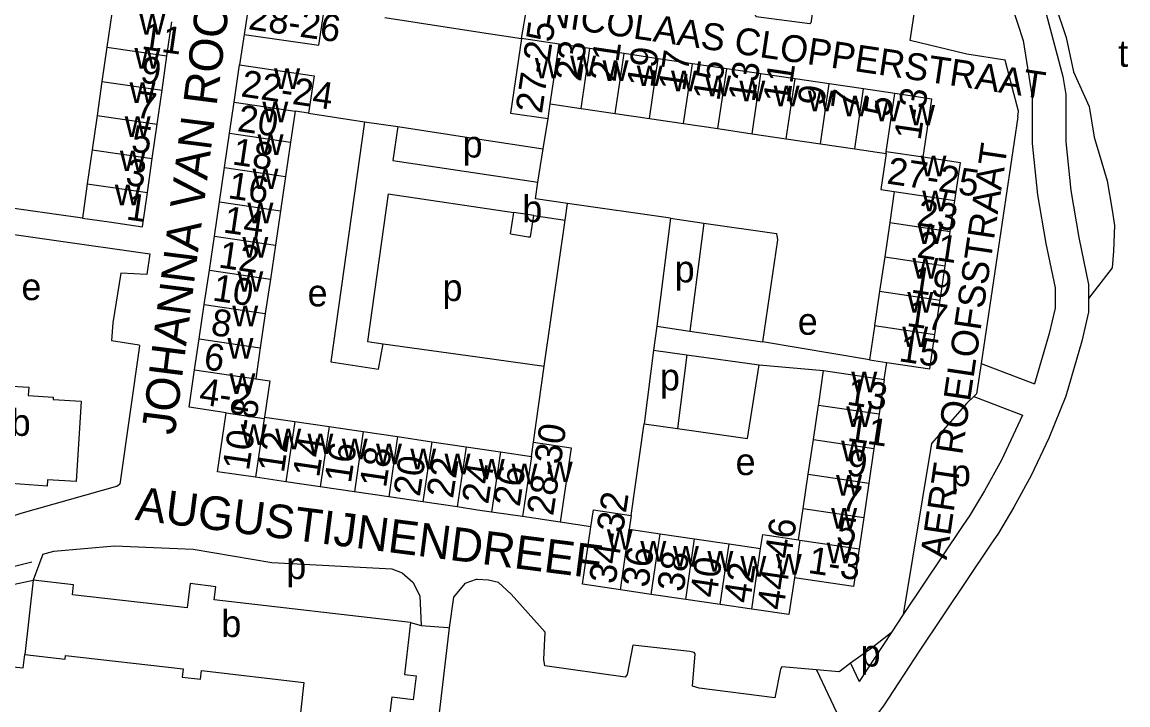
# Model space of a CAD drawing. Extents: x 160673 to 161924, y 382258 to 384145.
# Drawn here: x 161759.3 to 161924, y 383291.6 to 383393.3 of the extents above; entities that cross this region are included whole.
import ezdxf

# ---------------------------------------------------------------- set-up
doc = ezdxf.new("R2010")
doc.units = 0
for name, color, linetype in [('BLT_Basislijn', 7, 'Continuous'), ('BLT_Bebouwing', 7, 'Continuous'), ('BLT_Centroide', 7, 'Continuous'), ('BLT_Huisnummer', 7, 'Continuous'), ('BLT_Huisnummer_ tussenligend', 7, 'Continuous'), ('BLT_Huisnummer_reeks', 7, 'Continuous'), ('BLT_Onderverdeling_panden', 7, 'Continuous'), ('BLT_Straatnaam', 7, 'Continuous')]:
    doc.layers.add(name, color=color, linetype=linetype)

msp = doc.modelspace()

# ---------------------------------------------------------------- linework, layer by layer
at = {"layer": 'BLT_Basislijn'}
for p, q in [((161910.64, 383398.88), (161914.28, 383385.18)), ((161833.69, 383390.85), (161834.53, 383395.69)), ((161813.36, 383393.96), (161827.12, 383391.85)), ((161792.41, 383391.46), (161791.72, 383386.93)), ((161827.12, 383391.85), (161833.69, 383390.85)), ((161801.98, 383379.72), (161810.29, 383378.43)), ((161810.29, 383378.43), (161815.25, 383377.73)), ((161815.25, 383377.73), (161827.12, 383375.9)), ((161836.93, 383374.42), (161837.64, 383378.92)), ((161907.59, 383379.17), (161902.11, 383342.46)), ((161827.12, 383375.9), (161836.93, 383374.42)), ((161814.54, 383372.69), (161836.12, 383369.44)), ((161768.3, 383364.09), (161751.58, 383366.42)), ((161813.85, 383367.73), (161832.55, 383364.92)), ((161840.19, 383363.78), (161840.55, 383366.25)), ((161855.89, 383364.07), (161840.55, 383366.25)), ((161835.51, 383364.48), (161840.19, 383363.78)), ((161837.07, 383342.05), (161840.19, 383363.78)), ((161855.89, 383364.07), (161853.82, 383348)), ((161860.84, 383363.35), (161858.77, 383347.26)), ((161853.82, 383348), (161853.36, 383344.42)), ((161853.82, 383348), (161858.77, 383347.26)), ((161858.77, 383347.26), (161869.55, 383345.67)), ((161912.25, 383346.91), (161910.08, 383339.43)), ((161810.77, 383345.72), (161813.07, 383345.38)), ((161885.49, 383342.99), (161869.55, 383345.67)), ((161853.36, 383344.42), (161851.94, 383333.46)), ((161853.36, 383344.42), (161858.31, 383343.74)), ((161858.31, 383343.74), (161856.89, 383332.76)), ((161858.31, 383343.74), (161869.07, 383342.25)), ((161835.49, 383330.72), (161837.07, 383342.05)), ((161869.07, 383342.25), (161878.66, 383341.39)), ((161887.67, 383340.06), (161888.08, 383342.6)), ((161902.11, 383342.46), (161910.08, 383339.43)), ((161901.02, 383337.52), (161908.29, 383334.76)), ((161844.02, 383318.12), (161839.43, 383318.81)), ((161900.41, 383319.74), (161899.4, 383318.32)), ((161899.4, 383318.32), (161890.52, 383305.06)), ((161904.71, 383317.19), (161903.55, 383315.54)), ((161762.43, 383314.06), (161760.99, 383310.16)), ((161735.45, 383304.68), (161760.99, 383310.16)), ((161817.16, 383303.88), (161818.73, 383303.41)), ((161890.52, 383305.06), (161888.7, 383302.33)), ((161822.9, 383303.08), (161820.7, 383284.23)), ((161888.7, 383302.33), (161883.96, 383295.09)), ((161888.7, 383302.33), (161885.74, 383300.01)), ((161885.74, 383300.01), (161882.69, 383297.79)), ((161882.69, 383297.79), (161881.11, 383296.63)), ((161882.69, 383297.79), (161883.96, 383295.09)), ((161877.63, 383296.8), (161880.58, 383290.53))]:
    msp.add_line(p, q, dxfattribs=at)
for points in [[(161906.73, 383383.61), (161905.69, 383387.62), (161900, 383388.49), (161891.56, 383390.53), (161892.17, 383394.49), (161892.14, 383395.41), (161877.7, 383397.48), (161877.33, 383396.85), (161876.77, 383393.18), (161876.62, 383393.02), (161868.62, 383394.06), (161868.41, 383394.58), (161868.79, 383398.92), (161858.84, 383400.41)], [(161913.04, 383396.17), (161914.76, 383391.02), (161915.88, 383385.88)], [(161906.69, 383395.71), (161908.37, 383390.55), (161909.71, 383382.11), (161909.71, 383375.2), (161910.5, 383367.55), (161911.76, 383360.3), (161913.12, 383353.69), (161913.12, 383350.66), (161912.25, 383346.91)], [(161914.28, 383385.18), (161914.71, 383382.5), (161914.71, 383375.46), (161915.46, 383368.23), (161916.68, 383361.23), (161918.12, 383354.2), (161918.12, 383352.14)], [(161915.88, 383385.88), (161918.19, 383380.72), (161918.95, 383376.14), (161920.1, 383372.33), (161920.86, 383369.66), (161921.62, 383365.27), (161922, 383362.98), (161921.81, 383359.17), (161921.62, 383356.69), (161918.12, 383352.14)], [(161907.59, 383379.17), (161907.66, 383380.01), (161906.73, 383383.61)], [(161810.29, 383378.43), (161805.29, 383342.67), (161812.41, 383341.6), (161813.07, 383345.38)], [(161815.25, 383377.73), (161814.54, 383372.69)], [(161836.12, 383369.44), (161836.93, 383374.42)], [(161840.55, 383366.25), (161835.75, 383366.97), (161836.12, 383369.44)], [(161813.85, 383367.73), (161810.77, 383345.72)], [(161749.04, 383362.95), (161778.36, 383358.76), (161777.91, 383355.7), (161774.02, 383355.88), (161772.83, 383348.49), (161772.64, 383345.85), (161776.77, 383345.22), (161776.81, 383345.06), (161773.87, 383324.47), (161773.55, 383324.15), (161759.14, 383320.1), (161749.36, 383316.93), (161746.78, 383315.85), (161746.52, 383315.82)], [(161855.89, 383364.07), (161860.84, 383363.35)], [(161860.84, 383363.35), (161871.66, 383361.79), (161871.78, 383360.86), (161869.55, 383345.67)], [(161918.12, 383352.14), (161918.12, 383350.09), (161917.12, 383345.79)], [(161813.07, 383345.38), (161827.12, 383343.43)], [(161917.12, 383345.79), (161914.74, 383337.59), (161912.21, 383331.34), (161909.59, 383325.78), (161906.98, 383321.02), (161904.71, 383317.19)], [(161827.12, 383343.43), (161837.07, 383342.05)], [(161856.89, 383332.76), (161867.34, 383331.29), (161869.07, 383342.25)], [(161902.11, 383342.46), (161901.43, 383337.91), (161901.02, 383337.52)], [(161901.02, 383337.52), (161900, 383336.53), (161894.72, 383330.52), (161890.52, 383305.06)], [(161850.03, 383319.82), (161851.9, 383333.14), (161851.94, 383333.46)], [(161851.94, 383333.46), (161856.89, 383332.76)], [(161908.29, 383334.76), (161905.14, 383328.05), (161902.64, 383323.5), (161900.41, 383319.74)], [(161762.43, 383314.06), (161764.05, 383314.47), (161773.07, 383315.29), (161784.8, 383314.81), (161796.49, 383312.82), (161814.4, 383311.87), (161815.93, 383311.26), (161817.53, 383309.87), (161818.55, 383307.86), (161818.73, 383303.41)], [(161903.55, 383315.54), (161892.87, 383299.58), (161887.56, 383291.45), (161871.44, 383270.22)], [(161724.18, 383306.34), (161743.3, 383308.59), (161760.8, 383312.91)], [(161827.12, 383310.26), (161826.93, 383310.27), (161825.24, 383309.65), (161823.58, 383307.64), (161822.9, 383303.08)], [(161877.63, 383296.8), (161872.45, 383297.25), (161872.23, 383296.93), (161871.39, 383292.66), (161860.14, 383294.06), (161859.15, 383294.38), (161859.53, 383299.2), (161859.37, 383299.42), (161858.74, 383299.55), (161850.24, 383300.5), (161849.43, 383296.14), (161849.14, 383295.74), (161837.17, 383297.41), (161837.01, 383298.34), (161837.19, 383302.45), (161832.13, 383308.11), (161830.28, 383309.8), (161828.77, 383310.18), (161827.12, 383310.26)], [(161818.73, 383303.41), (161822.71, 383303.1), (161822.9, 383303.08)], [(161755, 383255.26), (161713.93, 383272.22), (161717.48, 383287.8), (161719.8, 383288.64), (161720.55, 383285.11), (161755.9, 383292.8), (161754.93, 383297.3), (161756.03, 383297.45), (161759.51, 383297.13), (161759.73, 383299.08)], [(161881.11, 383296.63), (161880.95, 383296.52), (161877.63, 383296.8)]]:
    msp.add_lwpolyline(points, dxfattribs=at)
at = {"layer": 'BLT_Bebouwing'}
for p, q in [((161793.23, 383397.06), (161792.41, 383391.46)), ((161772.68, 383394.62), (161771.95, 383389.54)), ((161780.9, 383388.26), (161781.63, 383393.34)), ((161839.28, 383390.02), (161833.69, 383390.85)), ((161771.95, 383389.54), (161771.22, 383384.45)), ((161843.87, 383389.35), (161839.28, 383390.02)), ((161848.96, 383388.59), (161843.87, 383389.35)), ((161780.17, 383383.17), (161780.9, 383388.26)), ((161854.05, 383387.84), (161848.96, 383388.59)), ((161859.15, 383387.09), (161854.05, 383387.84)), ((161790.9, 383381.36), (161791.72, 383386.93)), ((161864.24, 383386.34), (161859.15, 383387.09)), ((161869.33, 383385.58), (161864.24, 383386.34)), ((161771.22, 383384.45), (161770.49, 383379.36)), ((161874.42, 383384.83), (161869.33, 383385.58)), ((161879.51, 383384.08), (161874.42, 383384.83)), ((161779.44, 383378.08), (161780.17, 383383.17)), ((161884.61, 383383.33), (161879.51, 383384.08)), ((161889.28, 383382.64), (161884.61, 383383.33)), ((161790.22, 383376.73), (161790.9, 383381.36)), ((161837.64, 383378.92), (161837.97, 383381.11)), ((161837.97, 383381.11), (161842.55, 383380.43)), ((161770.49, 383379.36), (161769.76, 383374.27)), ((161799.99, 383380.02), (161799.3, 383375.39)), ((161801.98, 383379.72), (161799.99, 383380.02)), ((161847.64, 383379.68), (161852.74, 383378.92)), ((161778.71, 383372.99), (161779.44, 383378.08)), ((161852.74, 383378.92), (161857.83, 383378.17)), ((161857.83, 383378.17), (161862.92, 383377.42)), ((161789.46, 383371.63), (161790.22, 383376.73)), ((161862.92, 383377.42), (161868.01, 383376.67)), ((161868.01, 383376.67), (161873.1, 383375.91)), ((161873.1, 383375.91), (161878.2, 383375.16)), ((161878.2, 383375.16), (161883.29, 383374.41)), ((161883.29, 383374.41), (161887.96, 383373.72)), ((161769.76, 383374.27), (161769.03, 383369.18)), ((161777.98, 383367.9), (161778.71, 383372.99)), ((161788.71, 383366.53), (161789.46, 383371.63)), ((161798.55, 383370.29), (161797.8, 383365.19)), ((161769.03, 383369.18), (161768.3, 383364.09)), ((161889.19, 383368.06), (161888.51, 383363.44)), ((161787.96, 383361.43), (161788.71, 383366.53)), ((161897.52, 383362.11), (161898.2, 383366.73)), ((161797.8, 383365.19), (161797.05, 383360.09)), ((161832.07, 383361.73), (161832.55, 383364.92)), ((161835.51, 383364.48), (161832.55, 383364.92)), ((161888.51, 383363.44), (161887.76, 383358.33)), ((161787.21, 383356.33), (161787.96, 383361.43)), ((161896.77, 383357), (161897.52, 383362.11)), ((161797.05, 383360.09), (161796.3, 383354.99)), ((161887.76, 383358.33), (161887, 383353.22)), ((161786.46, 383351.23), (161787.21, 383356.33)), ((161896.01, 383351.89), (161896.77, 383357)), ((161796.3, 383354.99), (161795.54, 383349.89)), ((161887, 383353.22), (161886.24, 383348.1)), ((161895.25, 383346.77), (161896.01, 383351.89)), ((161785.7, 383346.13), (161786.46, 383351.23)), ((161795.54, 383349.89), (161794.79, 383344.79)), ((161785.02, 383341.51), (161785.7, 383346.13)), ((161794.79, 383344.79), (161794.11, 383340.17)), ((161885.49, 383342.99), (161888.08, 383342.6)), ((161878.66, 383341.39), (161887.67, 383340.06)), ((161887.67, 383340.06), (161886.92, 383334.92)), ((161877.15, 383331.11), (161877.9, 383336.25)), ((161886.92, 383334.92), (161886.16, 383329.78)), ((161795.41, 383334.47), (161799.93, 383333.8)), ((161799.93, 383333.8), (161805.03, 383333.05)), ((161805.03, 383333.05), (161810.13, 383332.3)), ((161810.13, 383332.3), (161815.24, 383331.55)), ((161815.24, 383331.55), (161820.34, 383330.79)), ((161820.34, 383330.79), (161825.44, 383330.04)), ((161835.17, 383328.61), (161835.49, 383330.72)), ((161876.39, 383325.97), (161877.15, 383331.11)), ((161830.55, 383329.29), (161835.17, 383328.61)), ((161886.16, 383329.78), (161885.4, 383324.64)), ((161798.6, 383324.83), (161794.09, 383325.49)), ((161875.63, 383320.84), (161876.39, 383325.97)), ((161803.71, 383324.08), (161798.6, 383324.83)), ((161808.81, 383323.32), (161803.71, 383324.08)), ((161813.91, 383322.57), (161808.81, 383323.32)), ((161885.4, 383324.64), (161884.64, 383319.51)), ((161819.02, 383321.82), (161813.91, 383322.57)), ((161824.12, 383321.07), (161819.02, 383321.82)), ((161827.12, 383320.62), (161824.12, 383321.07)), ((161829.22, 383320.31), (161827.12, 383320.62)), ((161833.85, 383319.63), (161829.22, 383320.31)), ((161874.94, 383316.17), (161875.63, 383320.84)), ((161839.43, 383318.81), (161833.85, 383319.63)), ((161850.03, 383319.82), (161849.74, 383317.76)), ((161884.64, 383319.51), (161883.95, 383314.84)), ((161849.74, 383317.76), (161854.34, 383317.08)), ((161859.46, 383316.33), (161864.59, 383315.57)), ((161864.59, 383315.57), (161869.29, 383314.88)), ((161883.95, 383314.84), (161883.13, 383309.23)), ((161760.99, 383310.16), (161759.73, 383299.08)), ((161883.13, 383309.23), (161874.31, 383310.53)), ((161853.01, 383308.06), (161848.41, 383308.74)), ((161858.13, 383307.31), (161853.01, 383308.06)), ((161863.26, 383306.55), (161858.13, 383307.31)), ((161867.96, 383305.86), (161863.26, 383306.55))]:
    msp.add_line(p, q, dxfattribs=at)
for points in [[(161792.41, 383391.46), (161803.51, 383389.84), (161804.33, 383395.43)], [(161833.69, 383390.85), (161832.05, 383379.74), (161837.64, 383378.92)], [(161791.72, 383386.93), (161802.8, 383385.3), (161801.98, 383379.72)], [(161893.51, 383373.15), (161894.79, 383381.82), (161889.28, 383382.64)], [(161842.55, 383380.43), (161842.91, 383380.37), (161847.64, 383379.68)], [(161799.3, 383375.39), (161799.26, 383375.07), (161798.55, 383370.29)], [(161887.96, 383373.72), (161887.17, 383368.36), (161889.19, 383368.06)], [(161898.2, 383366.73), (161899.03, 383372.34), (161893.51, 383373.15)], [(161768.3, 383364.09), (161772.3, 383363.52), (161777.25, 383362.81), (161777.98, 383367.9)], [(161832.07, 383361.73), (161834.71, 383361.33), (161835.02, 383361.29), (161835.51, 383364.48)], [(161886.24, 383348.1), (161886.22, 383347.93), (161885.49, 383342.99)], [(161888.08, 383342.6), (161894.5, 383341.65), (161895.25, 383346.77)], [(161789.69, 383335.11), (161784.2, 383335.92), (161785.02, 383341.51)], [(161794.11, 383340.17), (161796.21, 383339.86), (161795.41, 383334.47)], [(161877.9, 383336.25), (161877.93, 383336.44), (161878.66, 383341.39)], [(161747.91, 383338.11), (161751.9, 383337.85), (161751.92, 383338.2), (161756.91, 383337.88), (161756.99, 383339.13), (161760.32, 383338.92), (161760.24, 383337.67), (161763.97, 383337.43), (161763.94, 383337.08), (161768.15, 383336.81), (161767.38, 383324.85), (161763.13, 383325.12), (161763.07, 383324.19), (161750.97, 383325.05), (161751.04, 383325.99), (161747.07, 383326.28)], [(161794.09, 383325.49), (161788.4, 383326.33), (161789.69, 383335.11)], [(161825.44, 383330.04), (161827.12, 383329.79)], [(161835.49, 383330.72), (161841.06, 383329.9), (161839.43, 383318.81)], [(161827.12, 383329.79), (161830.23, 383329.33), (161830.55, 383329.29)], [(161844.02, 383318.12), (161844.39, 383320.65), (161850.03, 383319.82)], [(161848.41, 383308.74), (161842.76, 383309.58), (161844.02, 383318.12)], [(161854.34, 383317.08), (161854.68, 383317.03), (161859.46, 383316.33)], [(161869.29, 383314.88), (161869.6, 383316.96), (161874.94, 383316.17)], [(161817.16, 383303.88), (161787.92, 383307.23), (161788.17, 383309.2), (161784.35, 383309.68), (161783.89, 383306.04), (161766.83, 383307.98), (161766.99, 383309.47), (161760.99, 383310.16)], [(161874.31, 383310.53), (161873.51, 383305.04), (161867.96, 383305.86)], [(161817.16, 383303.88), (161816.27, 383296.13), (161817.99, 383295.94), (161817.58, 383292.35), (161814.38, 383292.72), (161808.98, 383249.99), (161808.89, 383249.27)], [(161759.73, 383299.08), (161765.73, 383298.39), (161765.8, 383298.97), (161783.31, 383296.96), (161783.16, 383295.74), (161785.9, 383295.41), (161786.05, 383296.7), (161801.29, 383294.95), (161799.69, 383280.5)]]:
    msp.add_lwpolyline(points, dxfattribs=at)
at = {"layer": 'BLT_Onderverdeling_panden'}
for p, q in [((161771.95, 383389.54), (161780.9, 383388.26)), ((161837.97, 383381.11), (161839.28, 383390.02)), ((161842.55, 383380.43), (161843.87, 383389.35)), ((161847.64, 383379.68), (161848.96, 383388.59)), ((161852.74, 383378.92), (161854.05, 383387.84)), ((161857.83, 383378.17), (161859.15, 383387.09)), ((161862.92, 383377.42), (161864.24, 383386.34)), ((161771.22, 383384.45), (161780.17, 383383.17)), ((161868.01, 383376.67), (161869.33, 383385.58)), ((161873.1, 383375.91), (161874.42, 383384.83)), ((161878.2, 383375.16), (161879.51, 383384.08)), ((161883.29, 383374.41), (161884.61, 383383.33)), ((161888, 383373.97), (161889.28, 383382.64)), ((161790.9, 383381.36), (161799.99, 383380.02)), ((161770.49, 383379.36), (161779.44, 383378.08)), ((161790.22, 383376.73), (161799.3, 383375.39)), ((161769.76, 383374.27), (161778.71, 383372.99)), ((161887.96, 383373.72), (161888, 383373.97)), ((161893.51, 383373.15), (161888, 383373.97)), ((161789.46, 383371.63), (161798.55, 383370.29)), ((161769.03, 383369.18), (161777.98, 383367.9)), ((161889.19, 383368.06), (161898.2, 383366.73)), ((161788.71, 383366.53), (161797.8, 383365.19)), ((161888.51, 383363.44), (161897.52, 383362.11)), ((161787.96, 383361.43), (161797.05, 383360.09)), ((161887.76, 383358.33), (161896.77, 383357)), ((161787.21, 383356.33), (161796.3, 383354.99)), ((161887, 383353.22), (161896.01, 383351.89)), ((161786.46, 383351.23), (161795.54, 383349.89)), ((161886.24, 383348.1), (161895.25, 383346.77)), ((161785.7, 383346.13), (161794.79, 383344.79)), ((161785.02, 383341.51), (161794.11, 383340.17)), ((161789.69, 383335.11), (161795.39, 383334.27)), ((161877.9, 383336.25), (161886.92, 383334.92)), ((161795.39, 383334.27), (161794.09, 383325.49)), ((161795.41, 383334.47), (161795.39, 383334.27)), ((161799.93, 383333.8), (161798.6, 383324.83)), ((161805.03, 383333.05), (161803.71, 383324.08)), ((161810.13, 383332.3), (161808.81, 383323.32)), ((161815.24, 383331.55), (161813.91, 383322.57)), ((161820.34, 383330.79), (161819.02, 383321.82)), ((161825.44, 383330.04), (161824.12, 383321.07)), ((161877.15, 383331.11), (161886.16, 383329.78)), ((161830.55, 383329.29), (161829.22, 383320.31)), ((161835.17, 383328.61), (161833.85, 383319.63)), ((161876.39, 383325.97), (161885.4, 383324.64)), ((161875.63, 383320.84), (161884.64, 383319.51)), ((161848.41, 383308.74), (161849.74, 383317.76)), ((161853.01, 383308.06), (161854.34, 383317.08)), ((161858.13, 383307.31), (161859.46, 383316.33)), ((161863.26, 383306.55), (161864.59, 383315.57)), ((161875.14, 383316.14), (161874.31, 383310.53)), ((161874.94, 383316.17), (161875.14, 383316.14)), ((161875.14, 383316.14), (161883.95, 383314.84)), ((161867.96, 383305.86), (161869.29, 383314.88))]:
    msp.add_line(p, q, dxfattribs=at)

# ---------------------------------------------------------------- texts
at = {"layer": 'BLT_Centroide'}
for s, p in [('w', (161776.79, 383391.44)), ('w', (161776.06, 383386.34)), ('t', (161922.52, 383386.63)), ('w', (161835.67, 383384.89)), ('w', (161840.92, 383385.22)), ('w', (161845.75, 383384.52)), ('w', (161796.85, 383383.31)), ('w', (161850.84, 383383.75)), ('w', (161855.94, 383383)), ('w', (161775.33, 383381.25)), ('w', (161861.03, 383382.25)), ('w', (161866.12, 383381.5)), ('w', (161871.22, 383380.75)), ('w', (161876.31, 383380)), ('w', (161795.1, 383378.38)), ('w', (161881.41, 383379.25)), ('w', (161886.28, 383378.53)), ('w', (161891.39, 383377.89)), ('w', (161774.6, 383376.19)), ('w', (161794.39, 383373.5)), ('p', (161824.93, 383373.12)), ('w', (161773.88, 383371.09)), ('w', (161893.1, 383370.34)), ('w', (161793.63, 383368.41)), ('w', (161773.14, 383366)), ('w', (161893.35, 383365.09)), ('w', (161792.88, 383363.31)), ('b', (161833.81, 383363.49)), ('w', (161892.63, 383360.22)), ('w', (161792.12, 383358.22)), ('w', (161891.88, 383355.09)), ('p', (161856.49, 383354.52)), ('e', (161759.23, 383351.88)), ('w', (161791.38, 383353.12)), ('p', (161821.93, 383351.75)), ('e', (161801.84, 383350.95)), ('w', (161891.13, 383350)), ('w', (161790.62, 383348)), ('e', (161874.82, 383346.72)), ('w', (161890.37, 383344.88)), ('w', (161789.91, 383343.16)), ('p', (161854.3, 383338.43)), ('w', (161790.2, 383337.91)), ('w', (161882.79, 383338.16)), ('b', (161757.63, 383331.66)), ('w', (161882.03, 383333)), ('w', (161791.89, 383330.3)), ('w', (161797.02, 383329.64)), ('w', (161801.81, 383328.94)), ('w', (161806.92, 383328.19)), ('w', (161812.02, 383327.44)), ('w', (161881.27, 383327.88)), ('w', (161817.12, 383326.69)), ('w', (161822.23, 383325.92)), ('e', (161865.56, 383325.82)), ('w', (161827.33, 383325.17)), ('w', (161832.2, 383324.45)), ('w', (161837.45, 383324.77)), ('p', (161897.62, 383324.17)), ('w', (161880.52, 383322.75)), ('w', (161879.79, 383317.84)), ('w', (161846.39, 383314.69)), ('w', (161851.38, 383312.92)), ('w', (161856.23, 383312.2)), ('w', (161879.13, 383312.69)), ('p', (161798.67, 383310.33)), ('w', (161861.36, 383311.44)), ('w', (161866.27, 383310.7)), ('w', (161871.55, 383311)), ('b', (161789, 383301.7)), ('p', (161884.16, 383297.31))]:
    msp.add_text(s, height=4, dxfattribs=at).set_placement(p)
at = {"layer": 'BLT_Huisnummer'}
for s, rotation, p in [('23', 81.5931, (161842.53, 383384.32)), ('19', 81.5931, (161853.27, 383383.39)), ('9', 351.8466, (161776.79, 383384.33)), ('15', 81.5931, (161863.13, 383381.43)), ('11', 81.5931, (161873.57, 383381.06)), ('7', 81.5931, (161883.69, 383379.99)), ('5', 351.8457, (161775.43, 383374.04)), ('18', 351.6114, (161790.49, 383372.11)), ('1', 351.8438, (161774.7, 383363.92)), ('23', 351.5915, (161892.45, 383363.02)), ('14', 351.6114, (161789.15, 383361.98)), ('19', 351.5905, (161891.57, 383353.03)), ('10', 351.6105, (161787.55, 383351.84)), ('15', 351.5968, (161889.74, 383342.8)), ('6', 351.6105, (161786.22, 383341.62)), ('13', 351.6101, (161881.98, 383336.33)), ('14', 81.6145, (161803.55, 383325.36)), ('18', 81.6145, (161813.51, 383323.82)), ('22', 81.6135, (161823.48, 383322.24)), ('9', 351.6101, (161881.93, 383325.84)), ('26', 81.6135, (161833.41, 383321)), ('5', 351.6101, (161880.41, 383315.68)), ('38', 81.6085, (161857.8, 383308.29)), ('42', 81.62, (161867.7, 383306.61))]:
    msp.add_text(s, height=4, rotation=rotation, dxfattribs=at).set_placement(p)
at = {"layer": 'BLT_Huisnummer_ tussenligend'}
for s, rotation, p in [('11', 351.8466, (161777, 383389.29)), ('21', 81.5931, (161847.67, 383384.26)), ('17', 81.5931, (161858.01, 383382.87)), ('13', 81.5931, (161868.37, 383381.26)), ('7', 351.8457, (161776.09, 383379.12)), ('9', 81.5931, (161878.7, 383380.68)), ('20', 351.6114, (161791.25, 383377.08)), ('5', 81.5931, (161888.6, 383379.07)), ('3', 351.8438, (161774.6, 383369.07)), ('16', 351.6114, (161789.85, 383367.08)), ('21', 351.5905, (161892.42, 383358.26)), ('12', 351.6105, (161788.44, 383356.76)), ('17', 351.5968, (161890.92, 383348.05)), ('8', 351.6105, (161787.29, 383346.72)), ('11', 351.6111, (161882.07, 383330.93)), ('12', 81.6145, (161798.3, 383326.05)), ('16', 81.6145, (161808.28, 383324.5)), ('20', 81.6145, (161818.54, 383322.51)), ('24', 81.6135, (161828.72, 383321.38)), ('7', 351.6101, (161881.08, 383320.59)), ('36', 81.6085, (161852.55, 383308.96)), ('40', 81.6085, (161862.7, 383307.43))]:
    msp.add_text(s, height=4, rotation=rotation, dxfattribs=at).set_placement(p)
at = {"layer": 'BLT_Huisnummer_reeks'}
for s, rotation, p in [('28-26', 351.6886, (161792.89, 383392.25)), ('27-25', 81.5931, (161836.72, 383379.57)), ('22-24', 351.6114, (161791.78, 383382.24)), ('1-3', 81.5943, (161893.09, 383375.57)), ('27-25', 351.5915, (161887.95, 383369.26)), ('4-2', 351.6101, (161785.55, 383336.39)), ('10-8', 81.6145, (161793.1, 383326.38)), ('28-30', 81.6082, (161838.39, 383319.65)), ('34-32', 81.6094, (161847.66, 383309.48)), ('44-46', 81.62, (161872.68, 383305.59)), ('1-3', 351.6088, (161876.22, 383311.26))]:
    msp.add_text(s, height=4, rotation=rotation, dxfattribs=at).set_placement(p)
at = {"layer": 'BLT_Straatnaam'}
for s, height, rotation, p in [('JOHANNA VAN ROCHEFORTSTRAAT', 5, 82.7709, (161782.06, 383331.69)), ('NICOLAAS CLOPPERSTRAAT', 4, 351.5952, (161836.96, 383392.83)), ('AERT ROELOFSSTRAAT', 4, 81.5952, (161896.98, 383313.14)), ('AUGUSTIJNENDREEF', 5, 352.732, (161776.05, 383319.17))]:
    msp.add_text(s, height=height, rotation=rotation, dxfattribs=at).set_placement(p)

doc.saveas('drawing.dxf')
